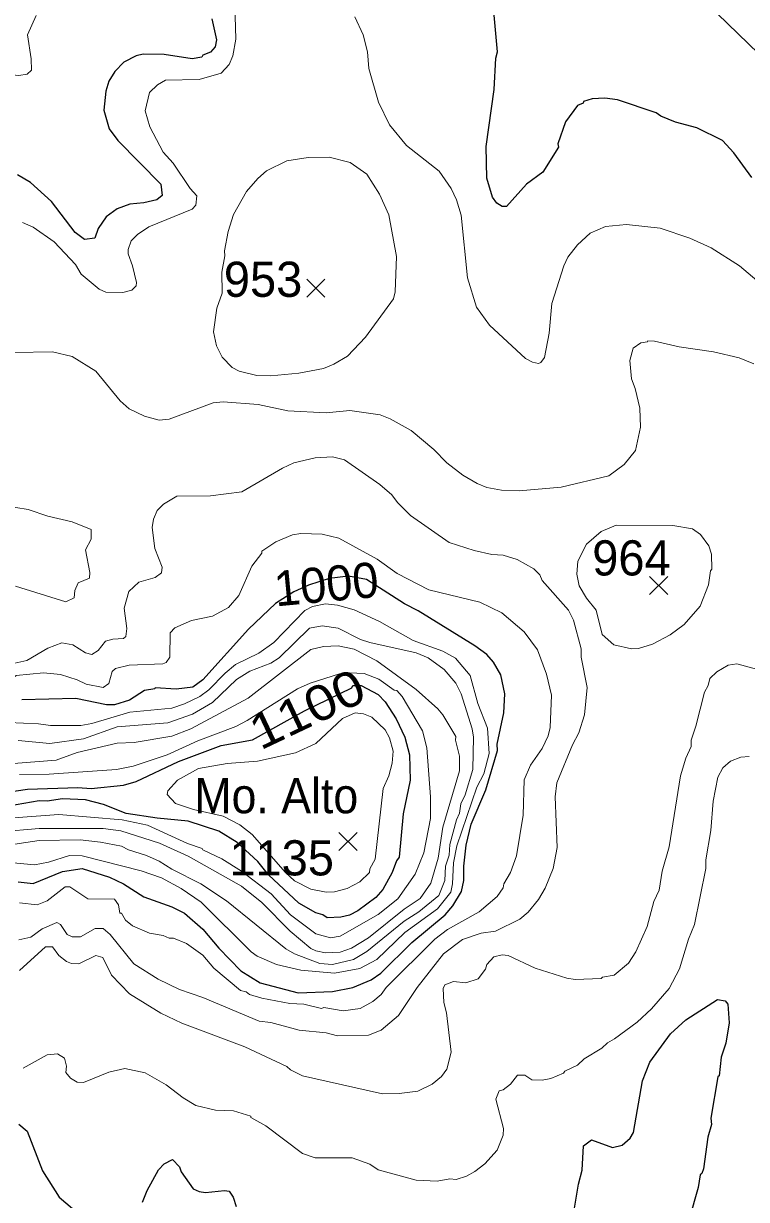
# Model space of a CAD drawing. Extents: x 265.7 to 292.1, y 7676.2 to 7704.2.
# Drawn here: x 278.272 to 279.917, y 7677.709 to 7680.384 of the extents above; entities that cross this region are included whole.
import ezdxf
from ezdxf.enums import TextEntityAlignment as Align

# ---------------------------------------------------------------- set-up
doc = ezdxf.new("R2010")
doc.units = 0
doc.header["$LTSCALE"] = 0.032
for name, color, linetype, lineweight in [('1', 7, 'Continuous', 25), ('2', 7, 'Continuous', 13), ('21', 7, 'Continuous', 25)]:
    doc.layers.add(name, color=color, linetype=linetype, lineweight=lineweight)
doc.layers.add('61', color=7, linetype='Continuous')

msp = doc.modelspace()

# ---------------------------------------------------------------- linework, layer by layer
at = {"layer": '1'}
for points in [[(279.7814, 7680.4741), (280.0143, 7680.2475)], [(279.4877, 7680.1102), (279.4893, 7680.1023), (279.4534, 7680.0456), (279.4167, 7680.0185), (279.3712, 7679.9674), (279.3616, 7679.9674), (279.3489, 7679.9746), (279.3393, 7679.9889), (279.3265, 7680.032), (279.3249, 7680.1039), (279.3433, 7680.2331), (279.3472, 7680.3049), (279.3504, 7680.3193), (279.3409, 7680.4278)], [(278.7009, 7680.3943), (278.7113, 7680.3464), (278.7081, 7680.3305), (278.6977, 7680.3185), (278.6802, 7680.3113), (278.6778, 7680.3073), (278.6562, 7680.3033), (278.5924, 7680.3129), (278.5445, 7680.3137), (278.5286, 7680.3097), (278.5006, 7680.2953), (278.4799, 7680.2746), (278.4663, 7680.2523), (278.4599, 7680.2299), (278.4551, 7680.1868), (278.4671, 7680.1438), (278.487, 7680.1174), (278.5844, 7680.0185), (278.5876, 7679.9921), (278.5756, 7679.9826), (278.5461, 7679.9754), (278.5142, 7679.973), (278.4855, 7679.9618), (278.4607, 7679.9435), (278.4424, 7679.9171), (278.4344, 7679.8956), (278.4113, 7679.8924), (278.3897, 7679.9083), (278.3362, 7679.9786), (278.2884, 7680.0217), (278.2588, 7680.0392)], [(279.5946, 7680.214), (279.5659, 7680.2124), (279.546, 7680.206), (279.5452, 7680.202), (279.5324, 7680.1972), (279.5052, 7680.1597), (279.4877, 7680.1102)], [(279.929, 7680.0336), (279.8883, 7680.0895), (279.8627, 7680.1174), (279.8037, 7680.1461), (279.7558, 7680.1589), (279.7223, 7680.1725), (279.7119, 7680.1805), (279.6234, 7680.21), (279.5946, 7680.214)], [(278.2604, 7678.4313), (278.2947, 7678.4273), (278.361, 7678.4545), (278.4057, 7678.4616), (278.4679, 7678.4417), (278.4998, 7678.4265), (278.5461, 7678.397), (278.6099, 7678.3739), (278.6387, 7678.3595), (278.6802, 7678.3236), (278.7169, 7678.2805), (278.7671, 7678.2286), (278.811, 7678.2015), (278.8972, 7678.1784), (278.9754, 7678.1816), (279.0217, 7678.1911), (279.0632, 7678.2079), (279.0855, 7678.223), (279.1557, 7678.2933), (279.2316, 7678.3563), (279.2491, 7678.3763), (279.269, 7678.409), (279.2738, 7678.4345), (279.2738, 7678.4664), (279.2794, 7678.5143), (279.2906, 7678.5622), (279.3241, 7678.6404), (279.3504, 7678.7298), (279.3496, 7678.7441), (279.3648, 7678.8159), (279.3672, 7678.859), (279.3584, 7678.9021), (279.3417, 7678.9309), (279.3265, 7678.9484), (279.2994, 7678.9683), (279.1701, 7679.0473), (279.139, 7679.0633), (279.0528, 7679.119), (279.0114, 7679.1266), (278.968, 7679.1209), (278.9209, 7679.1058), (278.887, 7679.0907), (278.8455, 7679.0643), (278.7839, 7679.0058), (278.6802, 7678.8909), (278.6578, 7678.8742), (278.6195, 7678.8694), (278.5716, 7678.8726), (278.5708, 7678.8702), (278.5477, 7678.8662), (278.5134, 7678.8447), (278.4791, 7678.8335), (278.4615, 7678.8335), (278.3913, 7678.8478), (278.2684, 7678.8455)], [(278.1519, 7678.6228), (278.2812, 7678.642), (278.3961, 7678.646), (278.4264, 7678.6436), (278.4998, 7678.6508), (278.5286, 7678.6595), (278.6251, 7678.705), (278.7217, 7678.7409), (278.7935, 7678.7545), (278.9116, 7678.8198), (279.0191, 7678.8726), (279.0217, 7678.8774), (279.0408, 7678.8774), (279.0791, 7678.8574), (279.0951, 7678.8407), (279.1198, 7678.8016), (279.1398, 7678.7601), (279.1502, 7678.7202)], [(279.1502, 7678.7202), (279.1517, 7678.6627), (279.1358, 7678.5861), (279.127, 7678.4872), (279.1206, 7678.4792), (279.1111, 7678.4521), (279.0895, 7678.4138)], [(279.0895, 7678.4138), (279.0735, 7678.3954), (279.0329, 7678.3651), (279.0137, 7678.3555), (278.9946, 7678.3507), (278.9634, 7678.3491), (278.9531, 7678.3563), (278.9371, 7678.3603), (278.8988, 7678.3826), (278.8298, 7678.4473), (278.8053, 7678.4775), (278.7582, 7678.5209), (278.7169, 7678.5462), (278.6467, 7678.5694), (278.5764, 7678.5757), (278.5062, 7678.5869), (278.4543, 7678.6069), (278.4136, 7678.618), (278.361, 7678.6196), (278.3259, 7678.6148), (278.3083, 7678.6156), (278.2205, 7678.6005)], [(279.5252, 7677.6844), (279.5348, 7677.7435), (279.5435, 7677.7754), (279.5459, 7677.8305), (279.5643, 7677.844), (279.6122, 7677.8265), (279.6345, 7677.832), (279.6521, 7677.848), (279.6601, 7677.8608), (279.6808, 7677.9781), (279.6968, 7678.0212), (279.7438, 7678.085), (279.7789, 7678.1169), (279.8508, 7678.1632), (279.8683, 7678.1608), (279.8747, 7678.1528), (279.8779, 7678.1105), (279.8699, 7678.0643), (279.8595, 7678.0323), (279.8548, 7677.9901), (279.8516, 7677.9877), (279.8356, 7677.8935), (279.8372, 7677.8791), (279.8292, 7677.8504), (279.8196, 7677.7786), (279.8157, 7677.7674), (279.8117, 7677.765), (279.8069, 7677.7355), (279.7869, 7677.6637)], [(278.262, 7677.8799), (278.2804, 7677.864), (278.3155, 7677.7738), (278.3538, 7677.714), (278.3993, 7677.6748)], [(278.5429, 7677.7028), (278.5533, 7677.7291), (278.5796, 7677.7762), (278.5924, 7677.7898), (278.6115, 7677.7993), (278.6275, 7677.7826), (278.6307, 7677.7714), (278.6586, 7677.7331), (278.6722, 7677.7267), (278.6865, 7677.7243), (278.7296, 7677.7291), (278.74, 7677.7275), (278.7496, 7677.7139), (278.756, 7677.6924)]]:
    msp.add_lwpolyline(points, dxfattribs=at)
at = {"layer": '2'}
for points in [[(278.3011, 7680.4015), (278.2812, 7680.3576), (278.29, 7680.3033), (278.2908, 7680.2778), (278.2804, 7680.2682), (278.262, 7680.265), (278.2221, 7680.269), (278.1982, 7680.2794), (278.1423, 7680.2938), (278.1088, 7680.2866), (278.0801, 7680.273), (278.0721, 7680.273), (278.0585, 7680.2802), (278.053, 7680.3129), (278.0538, 7680.3608), (278.0913, 7680.4478)], [(278.752, 7680.4534), (278.7552, 7680.348), (278.7488, 7680.3097), (278.74, 7680.2906), (278.7217, 7680.2706), (278.6722, 7680.2563), (278.5956, 7680.2547), (278.5772, 7680.2443), (278.5589, 7680.2267), (278.5493, 7680.1852), (278.5597, 7680.1485), (278.59, 7680.0911), (278.6131, 7680.0656), (278.6514, 7680.0081), (278.6666, 7679.9913), (278.6642, 7679.9706), (278.6562, 7679.961), (278.5573, 7679.9211), (278.5317, 7679.9036), (278.5174, 7679.8892), (278.5102, 7679.8693), (278.5102, 7679.8597), (278.5206, 7679.8325), (278.5293, 7679.7942), (278.5285, 7679.7871), (278.519, 7679.7767), (278.4982, 7679.7719), (278.4599, 7679.7727), (278.4448, 7679.7791), (278.4033, 7679.8134), (278.3905, 7679.8357), (278.3418, 7679.8868), (278.294, 7679.9203), (278.27, 7679.9307)], [(279.3321, 7679.6977), (279.3026, 7679.7384), (279.2826, 7679.8054), (279.2683, 7679.9475), (279.2571, 7679.9826), (279.2451, 7680.0081), (279.218, 7680.048), (279.1438, 7680.1062), (279.1047, 7680.1533), (279.0799, 7680.2044), (279.0576, 7680.281), (279.0552, 7680.3193), (279.0448, 7680.3576), (279.0257, 7680.3991)], [(279.9649, 7679.7783), (279.901, 7679.8325), (279.8364, 7679.8732), (279.7885, 7679.8956), (279.7207, 7679.9179), (279.6441, 7679.9267), (279.5962, 7679.9219), (279.5611, 7679.9068), (279.5324, 7679.8804), (279.5108, 7679.8517), (279.5013, 7679.8325), (279.4741, 7679.7464), (279.4685, 7679.6793)], [(279.4685, 7679.6793), (279.4574, 7679.6235), (279.4494, 7679.6123), (279.4438, 7679.6099), (279.4302, 7679.6131), (279.4143, 7679.6219), (279.3321, 7679.6977)], [(278.6036, 7679.4838), (278.5812, 7679.4814), (278.5477, 7679.4902), (278.5126, 7679.507), (278.4926, 7679.5253), (278.4368, 7679.5924), (278.3833, 7679.6259), (278.3386, 7679.637), (278.2509, 7679.6354)], [(279.9338, 7679.6091), (279.9002, 7679.6227), (279.842, 7679.637), (279.7638, 7679.6482), (279.7079, 7679.661), (279.6928, 7679.6618), (279.692, 7679.6594), (279.6768, 7679.657), (279.6593, 7679.645), (279.6513, 7679.6171), (279.6553, 7679.5756), (279.664, 7679.5533), (279.6744, 7679.5086), (279.676, 7679.4655), (279.6648, 7679.412), (279.6385, 7679.3801), (279.6042, 7679.3546), (279.4957, 7679.329), (279.3999, 7679.3202), (279.36, 7679.3218), (279.3265, 7679.3282), (279.3042, 7679.337), (279.2715, 7679.3562), (279.2355, 7679.3841), (279.206, 7679.4144), (279.1542, 7679.4575), (279.1063, 7679.4846), (279.0839, 7679.4934), (279.0145, 7679.503)], [(279.0145, 7679.503), (278.961, 7679.4982), (278.8733, 7679.5022), (278.8062, 7679.5166), (278.7264, 7679.5229), (278.7041, 7679.5205), (278.6036, 7679.4838)], [(278.2461, 7678.9269), (278.2796, 7678.9348), (278.3275, 7678.9628), (278.3594, 7678.9747), (278.3849, 7678.9699), (278.4136, 7678.9524), (278.428, 7678.9484), (278.4424, 7678.9572), (278.4591, 7678.9787), (278.4759, 7678.9835), (278.4998, 7678.9843), (278.5054, 7678.9891), (278.5078, 7679.0075), (278.5014, 7679.0537), (278.5118, 7679.0912), (278.5349, 7679.1128), (278.5716, 7679.1232), (278.586, 7679.1343), (278.5876, 7679.1471), (278.5708, 7679.1894), (278.5653, 7679.2373), (278.5684, 7679.2564), (278.5764, 7679.2756), (278.5908, 7679.2899), (278.6211, 7679.3083), (278.6977, 7679.3091), (278.7687, 7679.3179), (278.8613, 7679.3721), (278.8876, 7679.3841), (278.9355, 7679.3953), (278.9754, 7679.3977), (279.0025, 7679.3913), (279.0831, 7679.3346), (279.1103, 7679.3115), (279.123, 7679.2939), (279.1526, 7679.2644), (279.2403, 7679.2029), (279.2978, 7679.1846), (279.3377, 7679.1758), (279.3632, 7679.1742), (279.3951, 7679.1646), (279.4334, 7679.1431), (279.447, 7679.1295), (279.4526, 7679.1165)], [(278.2269, 7679.2875), (278.2828, 7679.278), (278.3275, 7679.2628), (278.3833, 7679.25), (278.4264, 7679.2325), (278.4264, 7679.2109), (278.4136, 7679.1862), (278.4232, 7679.1351), (278.4224, 7679.1216), (278.3969, 7679.1112), (278.3889, 7679.0936), (278.3873, 7679.0769), (278.369, 7679.0681), (278.2541, 7679.104)], [(278.2636, 7678.3834), (278.3035, 7678.3787), (278.3259, 7678.3882), (278.3674, 7678.4201), (278.3777, 7678.4201), (278.4184, 7678.3922), (278.4791, 7678.3914), (278.4886, 7678.3787), (278.4918, 7678.3595), (278.495, 7678.3595), (278.5046, 7678.3443), (278.5206, 7678.3308), (278.5589, 7678.314), (278.59, 7678.3092), (278.6036, 7678.3028), (278.6139, 7678.3028), (278.6435, 7678.2909), (278.6802, 7678.2645), (278.7057, 7678.235), (278.7663, 7678.184), (278.7791, 7678.1808), (278.7863, 7678.1752), (278.8142, 7678.1664), (278.8781, 7678.1544), (278.91, 7678.1528), (278.9499, 7678.1433), (278.9555, 7678.1449), (278.9993, 7678.1377), (279.0384, 7678.1433), (279.0672, 7678.1592), (279.0863, 7678.1752), (279.0975, 7678.1911), (279.2084, 7678.3005), (279.2371, 7678.3228), (279.309, 7678.3627), (279.3497, 7678.3978), (279.3632, 7678.4178), (279.3648, 7678.4265), (279.38, 7678.4521), (279.3935, 7678.4904), (279.4087, 7678.5829), (279.4111, 7678.6635), (279.4255, 7678.6963), (279.4526, 7678.7346), (279.4662, 7678.7633), (279.4701, 7678.7824), (279.4733, 7678.8558), (279.4622, 7678.9037), (279.4414, 7678.9588), (279.4111, 7678.9995), (279.3608, 7679.0434), (279.3106, 7679.0673), (279.1941, 7679.0952), (279.1222, 7679.1327), (279.0767, 7679.1654), (278.9898, 7679.2125), (278.9515, 7679.2221), (278.9036, 7679.2237), (278.8844, 7679.2205), (278.8461, 7679.2045), (278.8142, 7679.183), (278.8142, 7679.179), (278.7919, 7679.1495), (278.7623, 7679.0825), (278.7384, 7679.0553), (278.7025, 7679.0354), (278.6546, 7679.0258), (278.6163, 7679.009), (278.6059, 7678.9979), (278.6051, 7678.942), (278.5972, 7678.9301), (278.5892, 7678.9269), (278.5126, 7678.9237), (278.4815, 7678.9165), (278.4743, 7678.9093), (278.4663, 7678.8822), (278.4535, 7678.8734), (278.4152, 7678.8806), (278.3945, 7678.8909), (278.3562, 7678.9029)], [(279.4526, 7679.1165), (279.5124, 7679.0489), (279.5236, 7679.0266), (279.5412, 7678.9612), (279.5412, 7678.942), (279.5547, 7678.8734), (279.5483, 7678.8112), (279.5356, 7678.7697), (279.5212, 7678.7425), (279.4853, 7678.6564), (279.4821, 7678.6244), (279.4861, 7678.5095), (279.4773, 7678.4616), (279.459, 7678.417), (279.4438, 7678.3906), (279.4207, 7678.3619), (279.4015, 7678.3459), (279.3457, 7678.3188), (279.3137, 7678.314), (279.2707, 7678.2997), (279.2276, 7678.2677), (279.1677, 7678.1911), (279.1254, 7678.1273), (279.0863, 7678.0938), (279.0568, 7678.0826), (278.9866, 7678.081), (278.961, 7678.0874), (278.8996, 7678.0938), (278.835, 7678.1113), (278.8086, 7678.1145), (278.6802, 7678.168), (278.6275, 7678.1863), (278.5788, 7678.2095), (278.523, 7678.2446), (278.4695, 7678.3116), (278.4535, 7678.3252), (278.4352, 7678.3252), (278.4017, 7678.306), (278.3833, 7678.306), (278.3714, 7678.3116), (278.3562, 7678.334), (278.3482, 7678.3388), (278.3147, 7678.3244), (278.2892, 7678.3052), (278.262, 7678.2989)], [(278.6387, 7678.8359), (278.6738, 7678.8526), (278.6937, 7678.8678), (278.7312, 7678.9061), (278.7544, 7678.9253), (278.8078, 7678.9516), (278.8421, 7678.9755), (278.9124, 7679.0481), (278.9299, 7679.0577), (278.9595, 7679.0633), (278.9866, 7679.0601), (279.0249, 7679.0497), (279.0823, 7679.0234), (279.1589, 7678.9803), (279.226, 7678.9556), (279.2547, 7678.9396), (279.2882, 7678.9005), (279.3058, 7678.8367), (279.3281, 7678.7808), (279.3313, 7678.7234), (279.3193, 7678.6771), (279.3034, 7678.6468), (279.2579, 7678.5127), (279.2507, 7678.4744), (279.2483, 7678.4265), (279.2443, 7678.4074), (279.214, 7678.3699), (279.1398, 7678.3156), (279.076, 7678.2542), (279.0377, 7678.2342), (278.9802, 7678.223), (278.9036, 7678.2302), (278.8477, 7678.243), (278.8038, 7678.2621), (278.7903, 7678.2717), (278.6762, 7678.385), (278.6307, 7678.4162), (278.586, 7678.4401), (278.5397, 7678.4561), (278.4057, 7678.4904), (278.3769, 7678.4912), (278.3291, 7678.476), (278.2971, 7678.4696), (278.2253, 7678.4768)], [(278.2221, 7678.5119), (278.3083, 7678.5255), (278.4009, 7678.5263), (278.4472, 7678.5215), (278.495, 7678.5119), (278.511, 7678.5039), (278.5525, 7678.4912), (278.5812, 7678.4784), (278.6099, 7678.46), (278.6754, 7678.4265), (278.7344, 7678.3882), (278.8693, 7678.2789), (278.8892, 7678.2677), (278.9467, 7678.2454), (278.9754, 7678.243), (279.0233, 7678.2542), (279.0536, 7678.2725), (279.1382, 7678.3419), (279.1717, 7678.3627), (279.2172, 7678.4002), (279.2308, 7678.4345), (279.2323, 7678.4664), (279.2403, 7678.492), (279.2419, 7678.5159), (279.2571, 7678.5718), (279.2643, 7678.5877), (279.2675, 7678.6085), (279.277, 7678.6292), (279.2946, 7678.6867), (279.2962, 7678.7601), (279.293, 7678.7792), (279.2683, 7678.859), (279.2555, 7678.883), (279.2292, 7678.9141), (279.1932, 7678.9404), (279.1653, 7678.9524), (279.06, 7678.9755), (279.0392, 7678.9827), (278.9882, 7679.0082), (278.9515, 7679.0138), (278.9227, 7679.0082), (278.8541, 7678.9404), (278.835, 7678.9285), (278.7871, 7678.9101), (278.7568, 7678.8917), (278.7025, 7678.8391), (278.657, 7678.8127), (278.6004, 7678.7928), (278.4855, 7678.784), (278.4089, 7678.7561), (278.3323, 7678.7457), (278.2604, 7678.7529)], [(278.2493, 7678.7002), (278.3466, 7678.7082), (278.3945, 7678.725), (278.4855, 7678.7465), (278.5238, 7678.7481), (278.6099, 7678.7625), (278.653, 7678.7792), (278.7831, 7678.8486), (278.9259, 7678.9596), (278.9547, 7678.9668), (278.9882, 7678.9683), (279.0249, 7678.9604), (279.076, 7678.934), (279.1653, 7678.8686), (279.2148, 7678.8247), (279.226, 7678.8111), (279.2555, 7678.7617), (279.2547, 7678.7537), (279.2643, 7678.717), (279.2643, 7678.6835), (279.226, 7678.5558), (279.2156, 7678.4848), (279.1988, 7678.4281), (279.1749, 7678.393), (279.1382, 7678.3691), (279.0568, 7678.3036), (279.0185, 7678.2805), (278.993, 7678.2709), (278.9595, 7678.2693), (278.9371, 7678.2741), (278.9259, 7678.2797), (278.8789, 7678.3188), (278.8142, 7678.3842), (278.7679, 7678.4209), (278.6466, 7678.4896), (278.582, 7678.5191), (278.4934, 7678.547), (278.4535, 7678.5526), (278.3083, 7678.5526), (278.2189, 7678.5446)], [(278.2636, 7678.2294), (278.3227, 7678.2829), (278.3386, 7678.2829), (278.353, 7678.2638), (278.3698, 7678.2502), (278.3817, 7678.2454), (278.3985, 7678.2446), (278.4368, 7678.2637), (278.4527, 7678.259), (278.4727, 7678.2191), (278.5134, 7678.176), (278.5844, 7678.1321), (278.6323, 7678.1097), (278.7759, 7678.0555), (278.8717, 7678.0108), (278.8797, 7678.0036), (278.9068, 7677.99), (279.0887, 7677.9486), (279.127, 7677.9493), (279.1693, 7677.9549), (279.202, 7677.9709), (279.2236, 7677.9885), (279.2355, 7678.0052), (279.2451, 7678.0435), (279.2347, 7678.1329), (279.2284, 7678.1568), (279.2268, 7678.1887), (279.2308, 7678.1967), (279.2507, 7678.2047), (279.2786, 7678.2015), (279.3066, 7678.2103), (279.3233, 7678.2326), (279.3265, 7678.243), (279.3425, 7678.2606), (279.3616, 7678.2653), (279.3752, 7678.2637), (279.4366, 7678.235), (279.5084, 7678.2119), (279.5276, 7678.2087), (279.5866, 7678.2111), (279.5898, 7678.2143), (279.6162, 7678.2191), (279.6489, 7678.2462), (279.6656, 7678.2717), (279.6912, 7678.3292), (279.7063, 7678.3866), (279.7183, 7678.4122), (279.7255, 7678.4553), (279.7414, 7678.5111), (279.767, 7678.6723), (279.779, 7678.7122), (279.7909, 7678.7393), (279.7909, 7678.7537), (279.8021, 7678.7856), (279.8212, 7678.8622), (279.83, 7678.8774), (279.834, 7678.8933), (279.8492, 7678.9085), (279.8755, 7678.9237), (279.8947, 7678.9269), (279.9425, 7678.9141)], [(278.3562, 7678.9029), (278.3179, 7678.9069), (278.2556, 7678.9005), (278.2509, 7678.8965), (278.203, 7678.8838), (278.1551, 7678.8798), (278.0721, 7678.8941)], [(278.2189, 7678.5742), (278.353, 7678.5845), (278.4966, 7678.5718), (278.5541, 7678.5598), (278.6451, 7678.5183), (278.6786, 7678.5071), (278.6802, 7678.5039), (278.7233, 7678.4832), (278.7679, 7678.4553), (278.8358, 7678.4042), (278.8796, 7678.3563), (278.9371, 7678.3132), (278.9706, 7678.3036), (278.993, 7678.3076), (279.0791, 7678.3571), (279.1238, 7678.3922), (279.1637, 7678.4489), (279.1829, 7678.4968), (279.198, 7678.575), (279.198, 7678.6244), (279.1901, 7678.7361), (279.1797, 7678.7745), (279.1334, 7678.8527), (279.1214, 7678.8662), (279.1158, 7678.867), (279.0807, 7678.8925), (279.0472, 7678.9053), (279.0137, 7678.9069), (278.9914, 7678.9045), (278.9243, 7678.883), (278.8956, 7678.8702), (278.7815, 7678.7984), (278.7552, 7678.7848), (278.669, 7678.7521), (278.5988, 7678.7202), (278.5222, 7678.6946), (278.4839, 7678.6867), (278.3307, 7678.6763), (278.2636, 7678.6755)], [(278.3067, 7678.7904), (278.3338, 7678.7864), (278.4025, 7678.7864), (278.428, 7678.7912), (278.5142, 7678.8167), (278.6099, 7678.8263), (278.6387, 7678.8359)], [(278.1695, 7678.7968), (278.3067, 7678.7904)], [(279.3465, 7677.9366), (279.3544, 7677.9557), (279.3632, 7677.9581), (279.38, 7677.9709), (279.3959, 7677.9916), (279.4127, 7677.9916), (279.4287, 7677.9805), (279.4526, 7677.9797), (279.4717, 7677.9837), (279.5005, 7677.9956), (279.5037, 7678.0004), (279.5324, 7678.014), (279.5475, 7678.0284), (279.5882, 7678.0531), (279.601, 7678.0651), (279.617, 7678.0738), (279.668, 7678.1121), (279.7008, 7678.1425), (279.7414, 7678.1887), (279.7646, 7678.2334), (279.7853, 7678.3005), (279.7989, 7678.334), (279.8244, 7678.4616), (279.8244, 7678.4808), (279.8356, 7678.5478), (279.8412, 7678.6149), (279.8516, 7678.6691), (279.8635, 7678.6907), (279.8803, 7678.7058), (279.9042, 7678.7146), (279.9234, 7678.7162)], [(278.2716, 7678.0076), (278.3259, 7678.0379), (278.3498, 7678.0395), (278.3658, 7678.0299), (278.3705, 7678.0116), (278.369, 7677.9972), (278.3793, 7677.9845), (278.3945, 7677.9757), (278.4089, 7677.9749), (278.4663, 7677.998), (278.503, 7678.0068), (278.5493, 7677.9964), (278.5972, 7677.9693), (278.6355, 7677.9398), (278.6642, 7677.9222), (278.7089, 7677.9118), (278.7504, 7677.9103), (278.7895, 7677.8983), (278.7895, 7677.8951), (278.8238, 7677.8759), (278.9068, 7677.8129), (278.9355, 7677.8033), (279.0201, 7677.8033), (279.06, 7677.789), (279.0791, 7677.7762), (279.1653, 7677.7523), (279.2132, 7677.7499), (279.2419, 7677.7554), (279.2563, 7677.7539), (279.2802, 7677.7618)], [(279.2802, 7677.7618), (279.2994, 7677.7722), (279.3217, 7677.7898), (279.3496, 7677.8209), (279.3632, 7677.8552), (279.364, 7677.8704), (279.3465, 7677.9366)]]:
    msp.add_lwpolyline(points, dxfattribs=at)
for points in [[(278.7498, 7679.9492), (278.7799, 7680.0017), (278.8054, 7680.0312), (278.8254, 7680.0488), (278.8717, 7680.0711), (278.9196, 7680.0791), (278.9674, 7680.0799), (279.0153, 7680.0671), (279.0536, 7680.0408), (279.0823, 7679.9953), (279.1031, 7679.9482), (279.1206, 7679.8533), (279.1182, 7679.7735), (279.1142, 7679.7575), (279.0504, 7679.6698), (279.0097, 7679.6267), (278.9786, 7679.6083), (278.9547, 7679.5987), (278.8988, 7679.5884), (278.835, 7679.582), (278.8031, 7679.5828), (278.7632, 7679.5924), (278.7472, 7679.6011), (278.724, 7679.6243), (278.7113, 7679.6506), (278.7049, 7679.6825), (278.7121, 7679.736), (278.724, 7679.7703), (278.7232, 7679.8182), (278.7304, 7679.8549), (278.7296, 7679.8661), (278.7376, 7679.9107)], [(279.5313, 7679.1313), (279.5332, 7679.1607), (279.5531, 7679.199), (279.5866, 7679.2277), (279.6202, 7679.2421), (279.7494, 7679.242), (279.7941, 7679.2341), (279.8125, 7679.2213), (279.8316, 7679.1958), (279.8372, 7679.1766), (279.838, 7679.1423), (279.8348, 7679.1383), (279.8308, 7679.1064), (279.8117, 7679.0585), (279.775, 7679.0162), (279.7431, 7678.9931), (279.7032, 7678.9715), (279.6712, 7678.962), (279.6553, 7678.9612), (279.6154, 7678.9699), (279.589, 7678.9939), (279.5747, 7679.0489), (279.5531, 7679.0761), (279.5364, 7679.1048)], [(278.7929, 7678.539), (278.8683, 7678.4523), (278.889, 7678.4334), (278.9259, 7678.4146), (278.961, 7678.4074), (278.9802, 7678.4082), (279.0089, 7678.4162), (279.0377, 7678.4313), (279.0592, 7678.4521), (279.06, 7678.4608), (279.072, 7678.4824), (279.0903, 7678.6436), (279.1031, 7678.6723), (279.1111, 7678.701), (279.1135, 7678.7282), (279.1047, 7678.7585), (279.0951, 7678.7768), (279.0648, 7678.8056), (279.0456, 7678.8135), (279.0265, 7678.8159), (278.9978, 7678.8024), (278.9371, 7678.7457), (278.8908, 7678.7242), (278.8046, 7678.7058), (278.736, 7678.7002), (278.6706, 7678.6891), (278.6227, 7678.6627), (278.6004, 7678.638), (278.5988, 7678.63), (278.6179, 7678.6093), (278.6594, 7678.5957), (278.7264, 7678.5805), (278.7647, 7678.5606)]]:
    msp.add_lwpolyline(points, close=True, dxfattribs=at)
at = {"layer": '21'}
for p, q in [((278.9169, 7679.8022), (278.9581, 7679.761)), ((278.9581, 7679.8022), (278.9169, 7679.761)), ((279.6966, 7679.1258), (279.7378, 7679.0846)), ((279.7378, 7679.1258), (279.6966, 7679.0846)), ((278.9899, 7678.5433), (279.0311, 7678.5021)), ((279.0311, 7678.5433), (278.9899, 7678.5021))]:
    msp.add_line(p, q, dxfattribs=at)

# ---------------------------------------------------------------- texts
at = {"layer": '61'}
for s, p in [('953', (278.8173, 7679.7618)), ('964', (279.6553, 7679.128)), ('1135', (278.8596, 7678.4457))]:
    msp.add_text(s, height=0.08, dxfattribs=at).set_placement(p, align=Align.CENTER)
msp.add_text('1000', height=0.08, rotation=5.356, dxfattribs=at).set_placement((278.9647, 7679.0686), align=Align.CENTER)
at = {"layer": '61', "width": 1.15}
msp.add_text('1100', height=0.08, rotation=25.352, dxfattribs=at).set_placement((278.9347, 7678.788), align=Align.CENTER)
at = {"layer": '61', "width": 0.95}
msp.add_text('Mo. Alto', height=0.08, dxfattribs=at).set_placement((278.8474, 7678.5871), align=Align.CENTER)

doc.saveas('drawing.dxf')
